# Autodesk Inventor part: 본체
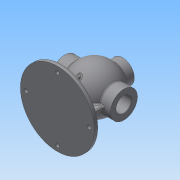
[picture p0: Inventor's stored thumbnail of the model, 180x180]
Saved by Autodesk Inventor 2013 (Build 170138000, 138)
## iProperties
Created: 2020-08
Part Number: 본체
Material: 일반
Document SubType Name: Modeling
Designer: 88
Density: 1 g/cm^3
Author: 88
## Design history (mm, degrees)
sketch "스케치3"
  geometry: L1 (-68, 0)-(68, 0); L2 (-68, 0)-(-68, 17.5); L3 (-68, 31)-(-42.988, 31); L4 (68, 0)-(68, 17.5); L5 (68, 31)-(42.988, 31); L6 (-52, 17.5)-(-52, 18.5); L7 (-52, 18.5)-(-50.25, 18.5); L8 (-50.25, 18.5)-(-50.25, 17.5); L9 (-50.25, 17.5)-(-39.278, 17.5); L10 (-52, 17.5)-(-68.035, 17.5); L11 (39.278, 17.5)-(68, 17.5); L12 (-68, 17.5)-(-68, 31); L13 (68, 17.5)-(68, 31); A1 r 53 centre (0, 0) between (42.988, 31) and (-42.988, 31); A2 r 43 centre (0, 0) between (39.278, 17.5) and (-39.278, 17.5); 2 further points
  constraints: 26 end point, 10 perpendicular, 4 point on circle, 3 coincident, 2 centre point, 2 horizontal, 1 collinear, 1 midpoint, 1 parallel, 1 point on line
  dimensions: "d0" = 53 radius of A1; "d1" = 43 radius of A2; "d2" = 136 distance of L1.start L1.end; "d3" = 62 diameter of L3 L1; "d4" = 62 diameter of L5 L1; "d5" = 37 diameter of L7 L1; "d6" = 1.75 distance of L6.end L7.end; "d13" = 35 diameter of L10 L1; "d14" = 35 diameter of L11 L1; "d15" = 16 distance between parallel lines of L2 L6
revolve "회전1" sketch "스케치3" stored, may be unused: angle "d16" = 90 deg
node "작업 평면1"
sketch "스케치4"
  geometry: C1 r 85 at (0, 0); 1 further point
  constraints: 1 centre point, 1 coincident
  dimensions: "d18" = 170 diameter of C1
extrude "돌출1" join sketch "스케치4" distance "d19" = 10; taper "d20" = 0 deg
sketch "스케치12"
  geometry: L1 (4, 43)-(-4, 43); L2 (-4, 43)-(-4, -43); L3 (-4, -43)-(4, -43); L4 (4, -43)-(4, 43); L5 (4, 43)-(-4, -43); L6 (-4, 43)-(4, -43); L7 (52, 4)-(-52, 4); L8 (-52, 4)-(-52, -4); L9 (-52, -4)-(52, -4); L10 (52, -4)-(52, 4); L11 (52, 4)-(-52, -4); L12 (-52, 4)-(52, -4); C1 r 85 at (0, 0) reference
  constraints: 24 end point, 4 midpoint, 4 parallel, 2 horizontal, 2 perpendicular
  dimensions: "d76" = 8 distance of L3.end L2.end; "d77" = 86 distance of L2.end L1.end; "d78" = 104 distance of L9.end L8.end; "d79" = 8 distance of L8.end L7.end
extrude "돌출5" join sketch "스케치12" stored distance "d80" = 52.75; taper "d81" = 0 deg
node "작업 평면2"
sketch "스케치6"
  geometry: C1 r 27 at (0, 0); 1 further point
  constraints: 1 centre point, 1 coincident
  dimensions: "d28" = 54 diameter of C1
extrude "돌출3" join sketch "스케치6" stored distance "d29" = 10; taper "d30" = 0 deg
sketch "스케치7"
  geometry: C1 r 27 at (0, 0) reference; C2 r 13 at (0, 0)
  constraints: 1 centre point, 1 coincident
  dimensions: "d31" = 26 diameter of C2
extrude "돌출4" cut sketch "스케치7" distance "d32" = 52.75; taper "d33" = 0 deg
sketch "스케치8"
  geometry: C1 r 13 at (0, 0) reference; 1 further point
  constraints: 1 vertical alignment
  dimensions: "d34" = 20 distance of C1.centre point (0, 20)
hole "구멍1" sketch "스케치8" at (0, 20) diameter "d35" = 3.242; stored, may be unused: countersink angle "d39" = 90 deg, drill point angle "d41" = 118 deg; dims "d36" = 12, "d37" = 4, "d38" = 2, "d40" = 15
sketch "스케치9"
  geometry: C1 r 31 at (0, 0) reference; 1 further point
  constraints: 1 vertical alignment
  dimensions: "d45" = 24 distance of C1.centre point (0, 24)
hole "구멍2" sketch "스케치9" at (0, 24) diameter "d46" = 3.242; stored, may be unused: countersink angle "d50" = 90 deg, drill point angle "d52" = 118 deg; dims "d47" = 12, "d48" = 4, "d49" = 2, "d51" = 15
node "작업 평면3"
sketch "스케치10"
  geometry: L1 (-27, 0)-(27, 0) reference; L2 (-27, 0)-(-27, -19.393) reference; 2 further points
  constraints: 1 other
  dimensions: "d56" = 9 distance from line of L1 point (0, -9); "d57" = 27 distance from line of L2 point (0, -9)
feature "엠보싱1" sketch "스케치10" dims "d0" = 53, "d1" = 43, "d2" = 136, "d3" = 62, "d4" = 62, "d5" = 37, "d6" = 1.75, "d13" = 35, "d14" = 35, "d15" = 16, "d20" = 0, "d58" = 0.5, "d59" = 0
sketch "스케치11"
  geometry: C1 r 85 at (0, 0) reference; 1 further point
  constraints: 1 vertical alignment
  dimensions: "d60" = 72.5 distance of point (0, 72.5) C1.centre
hole "구멍3" sketch "스케치11" at (0, 72.5) diameter "d61" = 9; stored, may be unused: countersink angle "d65" = 90 deg, drill point angle "d67" = 118 deg; dims "d62" = 12, "d63" = 4, "d64" = 2, "d66" = 15
fillet "모깎기1" dims "d71" = 3
fillet "모깎기2" dims "d82" = 3
fillet "모깎기3" dims "d83" = 3
fillet "모깎기4" dims "d84" = 3
chamfer "모따기1" distance "d85" = 1; stored, may be unused: second distance "d86" = 2, angle "d87" = 45 deg
chamfer "모따기2" distance "d88" = 1; stored, may be unused: second distance "d89" = 2, angle "d90" = 45 deg
node "솔리드1"
pattern_circular "원형 패턴1" dims angle "d43" = 360 deg
pattern_circular "원형 패턴2" dims angle "d54" = 360 deg
mirror "대칭1"
pattern_circular "원형 패턴3" dims angle "d69" = 360 deg
other parameters: "d17" = -85
